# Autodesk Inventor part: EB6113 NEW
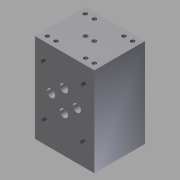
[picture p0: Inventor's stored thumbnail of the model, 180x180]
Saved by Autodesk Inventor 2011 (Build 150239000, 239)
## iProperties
Created: 2014-01
Part Number: EB6113 NEW
Document SubType Name: Modeling
Designer: Столбов
Density: 1 g/cm^3
Mass: 129.656 g
Surface Area: 256.845 cm^2
Volume: 129.656 cm^3
Author: Столбов
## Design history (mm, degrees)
sketch "Эскиз1"
  geometry: L1 (0, 0)-(48, 0); L2 (48, 0)-(48, 41); L3 (48, 41)-(0, 41); L4 (0, 41)-(0, 0)
  constraints: 8 end point, 2 parallel, 1 horizontal, 1 perpendicular
  dimensions: "d0" = 48 distance of L3.end L2.end; "d1" = 41 distance of L2.end L1.end
extrude "Выдавливание1" new body sketch "Эскиз1" distance "d2" = 72; taper "d3" = 0 deg
derived "Место под  CETOP03.ipt"
feature "Переместить тело1"
feature "Переместить тело2"
feature "Переместить тело3"
feature "Комбинировать1"
  node "Твердое тело2"
sketch "Эскиз2"
  geometry: L1 (48, -72)-(0, -72) reference; L2 (0, 0)-(0, -72) reference; L3 (0, 0)-(48, 0) reference; L4 (48, 0)-(48, -72) reference; C1 r 3.25 at (23.5, -47.2) reference; C2 r 3.25 at (23.5, -29.7) reference; C3 r 3.25 at (33.9, -38.5) reference; C4 r 3.25 at (13.1, -38.5) reference; C5 r 2.5 at (7.25, -57.5) reference; C6 r 2.5 at (39.75, -57.5) reference; C7 r 2.5 at (39, -17) reference; C8 r 2.5 at (8, -17) reference
extrude "Выдавливание2" cut sketch "Эскиз2" distance "d10" = 25; taper "d11" = 0 deg
sketch "Эскиз3"
  geometry: C1 r 3.25 at (13.1, -38.5) reference; C2 r 3.25 at (33.9, -38.5) reference; C3 r 3.25 at (23.5, -29.7) reference; C4 r 3.25 at (23.5, -47.2) reference; C5 r 6 at (13.1, -38.5); C6 r 6 at (23.5, -47.2); C7 r 6 at (33.9, -38.5); C8 r 6 at (23.5, -29.7)
  constraints: 4 centre point, 4 coincident
  dimensions: "d12" = 12 diameter of C5; "d13" = 12 diameter of C6; "d14" = 12 diameter of C7; "d15" = 12 diameter of C8
extrude "Выдавливание3" cut sketch "Эскиз3" distance "d16" = 1.5; taper "d17" = 0 deg
sketch "Эскиз4"
  geometry: L1 (0, 0)-(0, 41) reference; L2 (48, 0)-(0, 0) reference; L3 (48, 41)-(48, 0) reference; L4 (0, 41)-(48, 41) reference; L5 (0, 5)-(48, 5); L6 (48, 0)-(48, 41) reference; L7 (0, 36)-(48, 36); L8 (43, 0)-(43, 41); L9 (48, 41)-(0, 41) reference; L10 (5, 0)-(5, 41); L11 (16.35, 0)-(9.85, 0) reference; L12 (12, 0)-(12, 41); L13 (7.1, 41)-(19.1, 41) reference; L14 (36, 0)-(36, 41); L15 (27.9, 41)-(39.9, 41) reference; L16 (4.75, 41)-(4.75, 0) reference; 8 further points
  constraints: 28 point on line, 12 end point, 6 perpendicular
  dimensions: "d18" = 5 distance between parallel lines of L5 L2; "d19" = 5 distance between parallel lines of L4 L7; "d20" = 5 distance between parallel lines of L1 L10; "d21" = 5 distance between parallel lines of L8 L3; "d22" = 12 distance between parallel lines of L1 L12; "d23" = 12 distance between parallel lines of L6 L14
hole "Отверстие1" sketch "Эскиз4" at (5, 5), (4.75, 36), (12, 36), (12, 5), (36, 5), (36, 36), (43, 36), (43, 5) diameter "d24" = 3.242; stored, may be unused: countersink angle "d28" = 90 deg, drill point angle "d30" = 118 deg; dims "d25" = 6, "d26" = 4, "d27" = 2, "d29" = 13
sketch "Эскиз5"
  geometry: C1 r 1.621 at (-4.75, 36) reference; C2 r 1.621 at (-12, 36) reference; C3 r 1.621 at (-36, 36) reference; C4 r 1.621 at (-36, 36) reference; C5 r 1.621 at (-43, 36) reference; C6 r 1.621 at (-43, 5) reference; C7 r 1.621 at (-36, 5) reference; C8 r 1.621 at (-36, 5) reference; C9 r 1.621 at (-12, 5) reference; C10 r 1.621 at (-12, 5) reference; C11 r 1.621 at (-5, 5) reference; A1 r 1.621 centre (-4.75, 36) between (-5.25, 34.458) and (-5.25, 37.542) reference; A2 r 1.621 centre (-43, 36) between (-41.75, 37.032) and (-41.75, 34.968) reference; A3 r 1.621 centre (-43, 5) between (-41.75, 6.032) and (-41.75, 3.968) reference; 8 further points
  constraints: 8 coincident, 3 vertical alignment
hole "Отверстие2" sketch "Эскиз5" at (-4.75, 36), (-5, 5), (-12, 5), (-12, 36), (-36, 36), (-43, 36), (-43, 5), (-36, 5) diameter "d31" = 3.242; stored, may be unused: countersink angle "d35" = 90 deg, drill point angle "d37" = 118 deg; dims "d32" = 6, "d33" = 4, "d34" = 2, "d36" = 13
sketch "Эскиз6"
  geometry: L1 (5, 5)-(36, 36); L2 (36, 36)-(36, 5); L3 (37.15, 39.5)-(37.15, 0) reference; L4 (36, 5)-(4.75, 36); C1 r 1.621 at (36, 36) reference; C2 r 1.621 at (36, 5) reference; C3 r 1.621 at (4.75, 36) reference; C4 r 1.621 at (5, 5) reference; 1 further point
  constraints: 6 end point, 2 point on line, 1 parallel
hole "Отверстие3" sketch "Эскиз6" at (20.438, 20.438) diameter "d38" = 3.5; stored, may be unused: countersink angle "d42" = 90 deg, drill point angle "d44" = 118 deg; dims "d39" = 6, "d40" = 4, "d41" = 2, "d43" = 26
sketch "Эскиз7"
  geometry: C1 r 1.75 at (-20.438, 20.438) reference; 1 further point
  constraints: 1 coincident
hole "Отверстие4" sketch "Эскиз7" at (-20.438, 20.438) diameter "d45" = 3.5; stored, may be unused: countersink angle "d49" = 90 deg, drill point angle "d51" = 118 deg; dims "d46" = 6, "d47" = 4, "d48" = 2, "d50" = 30
sketch "Эскиз8"
  geometry: L1 (0, 41)-(48, 41) reference; L2 (43, 5)-(12, 36); L3 (12, 36)-(12, 5); L4 (12, 5)-(43, 36); C1 r 1.621 at (12, 5) reference; C2 r 1.621 at (12, 36) reference; C3 r 1.621 at (43, 5) reference; C4 r 1.621 at (43, 36) reference; C5 r 1.75 at (27.5, 20.5); 1 further point
  constraints: 6 end point, 2 perpendicular, 1 centre point, 1 coincident, 1 midpoint
  dimensions: "d53" = 3.5 diameter of C5
node "РабПлоскость1"
sketch "Эскиз9"
  geometry: L1 (27.5, -72)-(33.9, -38.5); C1 r 3.25 at (33.9, -38.5) reference; 1 further point
  constraints: 2 end point
feature "Сдвиг1" sketch "Эскиз9" dims "d54" = 0
sketch "Эскиз10"
  geometry: C1 r 1.75 at (-27.5, 20.5) reference
sketch "Эскиз11"
  geometry: L1 (29.25, 0)-(25.75, 0) reference; L2 (27.5, 0)-(33.9, -38.5); C1 r 3.25 at (33.9, -38.5) reference; 1 further point
  constraints: 2 end point, 1 midpoint
feature "Сдвиг2" sketch "Эскиз10", "Эскиз11" dims "d55" = 0
node "Твердое тело1"
feature "Твердое тело1::Место под  CETOP03.ipt" dims "d4" = 10
tag "Элемент создания маркировки1"
node "Спроецированная петля1"
node "Спроецированная петля2"
node "Спроецированная петля3"
node "Спроецированная петля4"
node "Спроецированная петля5"
node "Спроецированная петля6"
node "Спроецированная петля7"
other parameters: "d5" = 90 deg, "d6" = 90 deg, "d7" = 8, "d8" = 8, "d9" = 17, "d52" = -20.5
